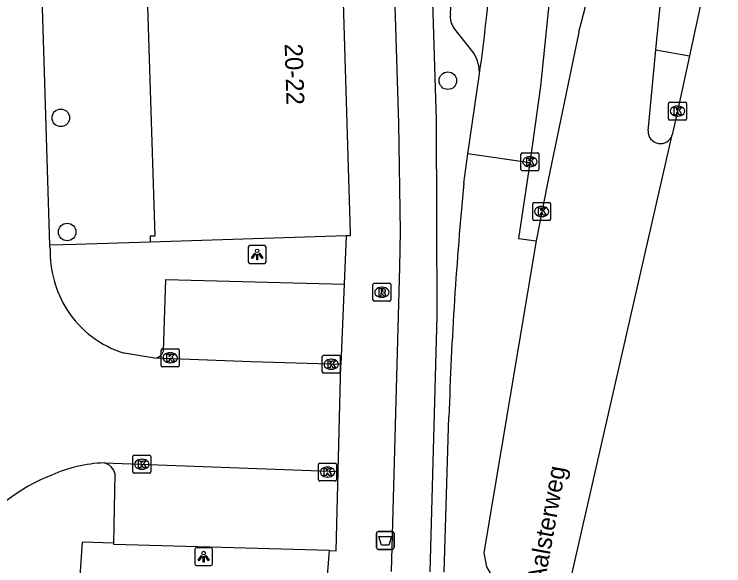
# Model space of a CAD drawing. Extents: x 161402 to 161933, y 381650 to 382313.
# Drawn here: x 161889.94 to 161929.57, y 382075.91 to 382106.69 of the extents above; entities that cross this region are included whole.
import ezdxf

# ---------------------------------------------------------------- set-up
doc = ezdxf.new("R2010")
doc.units = 0
for name, color, linetype in [('IMGEO_Afvalbak', 7, 'Continuous'), ('IMGEO_Boom', 7, 'Continuous'), ('IMGEO_Fietspad_open', 7, 'Continuous'), ('IMGEO_Kolk', 7, 'Continuous'), ('IMGEO_Lichtpunt', 7, 'Continuous'), ('IMGEO_Muur', 7, 'Continuous'), ('IMGEO_Openbare_ruimte_label', 7, 'Continuous'), ('IMGEO_OVBaan_gesloten', 7, 'Continuous'), ('IMGEO_Pand', 7, 'Continuous'), ('IMGEO_Pand_nummerreeks', 7, 'Continuous'), ('IMGEO_Parkeervlak_open', 7, 'Continuous'), ('IMGEO_Rijbaan_lokaal_gesloten', 7, 'Continuous'), ('IMGEO_Rijbaan_lokaal_open', 7, 'Continuous'), ('IMGEO_Rioolput', 7, 'Continuous'), ('IMGEO_Verkeerseiland_open', 7, 'Continuous'), ('IMGEO_Voetpad_open', 7, 'Continuous')]:
    doc.layers.add(name, color=color, linetype=linetype)

msp = doc.modelspace()

# ---------------------------------------------------------------- linework, layer by layer
at = {"layer": 'IMGEO_Afvalbak'}
for p, q in [((161910.171, 382076.92), (161910.171, 382077.72)), ((161910.171, 382077.72), (161910.171, 382076.92)), ((161910.271, 382077.82), (161911.061, 382077.82)), ((161911.061, 382077.82), (161910.271, 382077.82)), ((161911.161, 382077.72), (161911.161, 382076.92)), ((161911.161, 382076.92), (161911.161, 382077.72)), ((161911.061, 382076.82), (161910.271, 382076.82)), ((161910.271, 382076.82), (161911.061, 382076.82))]:
    msp.add_line(p, q, dxfattribs=at)
msp.add_lwpolyline([(161910.314, 382077.534), (161911.018, 382077.534), (161910.869, 382077.064), (161910.463, 382077.064), (161910.314, 382077.534)], dxfattribs=at)
for centre, start, end in [((161910.271, 382077.72), 90, 180), ((161910.271, 382077.72), 90, 180), ((161911.061, 382077.72), 0, 90), ((161911.061, 382077.72), 360, 90), ((161910.271, 382076.92), 180, 270), ((161910.271, 382076.92), 180, 270), ((161911.061, 382076.92), 270, 0), ((161911.061, 382076.92), 270, 0)]:
    msp.add_arc(centre, 0.1, start, end, dxfattribs=at)
at = {"layer": 'IMGEO_Boom'}
for centre in [(161914.164, 382102.973), (161892.545, 382100.904), (161892.901, 382094.534)]:
    msp.add_circle(centre, 0.489, dxfattribs=at)
at = {"layer": 'IMGEO_Fietspad_open'}
for points in [[(161911.019, 382075.595), (161911.485, 382092.573), (161911.516, 382094.566), (161911.423, 382100.579), (161910.052, 382144.744)], [(161912.16, 382144.813), (161912.252, 382141.473), (161913.518, 382100.778), (161913.546, 382089.832), (161913.149, 382075.567)]]:
    msp.add_lwpolyline(points, dxfattribs=at)
at = {"layer": 'IMGEO_Kolk'}
for p, q in [((161926.487, 382100.851), (161926.487, 382101.703)), ((161926.562, 382101.777), (161927.414, 382101.777)), ((161926.975, 382101.557), (161927, 382101.557)), ((161927.488, 382101.703), (161927.488, 382100.851)), ((161927.414, 382100.777), (161926.562, 382100.777)), ((161926.998, 382100.997), (161926.973, 382100.997)), ((161918.246, 382098.026), (161918.246, 382098.878)), ((161918.321, 382098.952), (161919.173, 382098.952)), ((161918.734, 382098.732), (161918.759, 382098.732)), ((161919.247, 382098.878), (161919.247, 382098.026)), ((161919.173, 382097.952), (161918.321, 382097.952)), ((161918.757, 382098.172), (161918.732, 382098.172)), ((161918.901, 382095.25), (161918.901, 382096.102)), ((161918.976, 382096.176), (161919.828, 382096.176)), ((161919.389, 382095.956), (161919.414, 382095.956)), ((161919.902, 382096.102), (161919.902, 382095.25)), ((161919.828, 382095.176), (161918.976, 382095.176)), ((161919.412, 382095.396), (161919.387, 382095.396)), ((161898.23, 382088.013), (161899.082, 382088.013)), ((161898.155, 382087.087), (161898.155, 382087.939)), ((161898.643, 382087.793), (161898.668, 382087.793)), ((161899.156, 382087.939), (161899.156, 382087.087)), ((161907.149, 382086.726), (161907.149, 382087.578)), ((161907.224, 382087.652), (161908.076, 382087.652)), ((161908.15, 382087.578), (161908.15, 382086.726)), ((161898.666, 382087.233), (161898.641, 382087.233)), ((161907.637, 382087.432), (161907.662, 382087.432)), ((161899.082, 382087.013), (161898.23, 382087.013)), ((161907.66, 382086.872), (161907.635, 382086.872)), ((161908.076, 382086.652), (161907.224, 382086.652)), ((161896.643, 382082.074), (161897.495, 382082.074)), ((161896.568, 382081.148), (161896.568, 382082)), ((161897.056, 382081.854), (161897.081, 382081.854)), ((161897.569, 382082), (161897.569, 382081.148)), ((161907.014, 382081.64), (161907.866, 382081.64)), ((161897.079, 382081.294), (161897.054, 382081.294)), ((161906.939, 382080.714), (161906.939, 382081.566)), ((161907.427, 382081.42), (161907.452, 382081.42)), ((161907.94, 382081.566), (161907.94, 382080.714)), ((161897.495, 382081.074), (161896.643, 382081.074)), ((161907.45, 382080.86), (161907.425, 382080.86)), ((161907.866, 382080.64), (161907.014, 382080.64))]:
    msp.add_line(p, q, dxfattribs=at)
for points in [[(161926.487, 382100.851), (161926.487, 382101.703)], [(161926.562, 382101.777), (161927.414, 382101.777)], [(161926.808, 382101.477), (161926.931, 382101.477), (161926.931, 382101.326), (161927.061, 382101.477), (161927.225, 382101.477), (161927.079, 382101.326), (161927.232, 382101.077), (161927.08, 382101.077), (161926.995, 382101.241), (161926.931, 382101.174), (161926.931, 382101.077), (161926.808, 382101.077), (161926.808, 382101.477)], [(161927.488, 382101.703), (161927.488, 382100.851)], [(161927.414, 382100.777), (161926.562, 382100.777)], [(161918.246, 382098.026), (161918.246, 382098.878)], [(161918.321, 382098.952), (161919.173, 382098.952)], [(161918.567, 382098.652), (161918.69, 382098.652), (161918.69, 382098.501), (161918.82, 382098.652), (161918.984, 382098.652), (161918.838, 382098.501), (161918.991, 382098.252), (161918.839, 382098.252), (161918.754, 382098.416), (161918.69, 382098.349), (161918.69, 382098.252), (161918.567, 382098.252), (161918.567, 382098.652)], [(161919.247, 382098.878), (161919.247, 382098.026)], [(161919.173, 382097.952), (161918.321, 382097.952)], [(161918.901, 382095.25), (161918.901, 382096.102)], [(161918.976, 382096.176), (161919.828, 382096.176)], [(161919.902, 382096.102), (161919.902, 382095.25)], [(161919.222, 382095.876), (161919.345, 382095.876), (161919.345, 382095.725), (161919.475, 382095.876), (161919.639, 382095.876), (161919.493, 382095.725), (161919.646, 382095.476), (161919.494, 382095.476), (161919.409, 382095.64), (161919.345, 382095.573), (161919.345, 382095.476), (161919.222, 382095.476), (161919.222, 382095.876)], [(161919.828, 382095.176), (161918.976, 382095.176)], [(161898.23, 382088.013), (161899.082, 382088.013)], [(161898.155, 382087.087), (161898.155, 382087.939)], [(161898.476, 382087.713), (161898.599, 382087.713), (161898.599, 382087.562), (161898.729, 382087.713), (161898.893, 382087.713), (161898.747, 382087.562), (161898.9, 382087.313), (161898.748, 382087.313), (161898.663, 382087.477), (161898.599, 382087.41), (161898.599, 382087.313), (161898.476, 382087.313), (161898.476, 382087.713)], [(161899.156, 382087.939), (161899.156, 382087.087)], [(161907.149, 382086.726), (161907.149, 382087.578)], [(161907.224, 382087.652), (161908.076, 382087.652)], [(161908.15, 382087.578), (161908.15, 382086.726)], [(161907.47, 382087.352), (161907.593, 382087.352), (161907.593, 382087.201), (161907.723, 382087.352), (161907.887, 382087.352), (161907.741, 382087.201), (161907.894, 382086.952), (161907.742, 382086.952), (161907.657, 382087.116), (161907.593, 382087.049), (161907.593, 382086.952), (161907.47, 382086.952), (161907.47, 382087.352)], [(161899.082, 382087.013), (161898.23, 382087.013)], [(161908.076, 382086.652), (161907.224, 382086.652)], [(161896.643, 382082.074), (161897.495, 382082.074)], [(161896.568, 382081.148), (161896.568, 382082)], [(161896.889, 382081.774), (161897.012, 382081.774), (161897.012, 382081.623), (161897.142, 382081.774), (161897.306, 382081.774), (161897.16, 382081.623), (161897.313, 382081.374), (161897.161, 382081.374), (161897.076, 382081.538), (161897.012, 382081.471), (161897.012, 382081.374), (161896.889, 382081.374), (161896.889, 382081.774)], [(161897.569, 382082), (161897.569, 382081.148)], [(161907.014, 382081.64), (161907.866, 382081.64)], [(161906.939, 382080.714), (161906.939, 382081.566)], [(161907.26, 382081.34), (161907.383, 382081.34), (161907.383, 382081.189), (161907.513, 382081.34), (161907.677, 382081.34), (161907.531, 382081.189), (161907.684, 382080.94), (161907.532, 382080.94), (161907.447, 382081.104), (161907.383, 382081.037), (161907.383, 382080.94), (161907.26, 382080.94), (161907.26, 382081.34)], [(161907.94, 382081.566), (161907.94, 382080.714)], [(161897.495, 382081.074), (161896.643, 382081.074)], [(161907.866, 382080.64), (161907.014, 382080.64)]]:
    msp.add_lwpolyline(points, dxfattribs=at)
for centre, start, end in [((161926.564, 382101.701), 91.552, 178.448), ((161926.564, 382101.701), 91.552, 178.448), ((161927.412, 382101.701), 1.552, 88.448), ((161927.412, 382101.701), 1.552, 88.448), ((161926.564, 382100.853), 181.552, 268.448), ((161926.564, 382100.853), 181.552, 268.448), ((161927.412, 382100.853), 271.552, 358.448), ((161927.412, 382100.853), 271.552, 358.448), ((161918.323, 382098.876), 91.552, 178.448), ((161918.323, 382098.876), 91.552, 178.448), ((161919.171, 382098.876), 1.552, 88.448), ((161919.171, 382098.876), 1.552, 88.448), ((161918.323, 382098.028), 181.552, 268.448), ((161918.323, 382098.028), 181.552, 268.448), ((161919.171, 382098.028), 271.552, 358.448), ((161919.171, 382098.028), 271.552, 358.448), ((161918.978, 382096.1), 91.552, 178.448), ((161918.978, 382096.1), 91.552, 178.448), ((161919.826, 382096.1), 1.552, 88.448), ((161919.826, 382096.1), 1.552, 88.448), ((161918.978, 382095.252), 181.552, 268.448), ((161918.978, 382095.252), 181.552, 268.448), ((161919.826, 382095.252), 271.552, 358.448), ((161919.826, 382095.252), 271.552, 358.448), ((161898.232, 382087.937), 91.552, 178.448), ((161898.232, 382087.937), 91.552, 178.448), ((161899.08, 382087.937), 1.552, 88.448), ((161899.08, 382087.937), 1.552, 88.448), ((161907.226, 382087.576), 91.552, 178.448), ((161907.226, 382087.576), 91.552, 178.448), ((161908.074, 382087.576), 1.552, 88.448), ((161908.074, 382087.576), 1.552, 88.448), ((161898.232, 382087.089), 181.552, 268.448), ((161898.232, 382087.089), 181.552, 268.448), ((161899.08, 382087.089), 271.552, 358.448), ((161899.08, 382087.089), 271.552, 358.448), ((161907.226, 382086.728), 181.552, 268.448), ((161907.226, 382086.728), 181.552, 268.448), ((161908.074, 382086.728), 271.552, 358.448), ((161908.074, 382086.728), 271.552, 358.448), ((161896.645, 382081.998), 91.552, 178.448), ((161896.645, 382081.998), 91.552, 178.448), ((161897.493, 382081.998), 1.552, 88.448), ((161897.493, 382081.998), 1.552, 88.448), ((161907.016, 382081.564), 91.552, 178.448), ((161907.016, 382081.564), 91.552, 178.448), ((161907.864, 382081.564), 1.552, 88.448), ((161907.864, 382081.564), 1.552, 88.448), ((161896.645, 382081.15), 181.552, 268.448), ((161896.645, 382081.15), 181.552, 268.448), ((161897.493, 382081.15), 271.552, 358.448), ((161897.493, 382081.15), 271.552, 358.448), ((161907.016, 382080.716), 181.552, 268.448), ((161907.016, 382080.716), 181.552, 268.448), ((161907.864, 382080.716), 271.552, 358.448), ((161907.864, 382080.716), 271.552, 358.448)]:
    msp.add_arc(centre, 0.0765, start, end, dxfattribs=at)
for centre, major_axis, ratio, start_param, end_param in [((161926.974, 382101.277), (-0.387, 0.002), 0.722429, 4.712389, 7.853982), ((161926.999, 382101.277), (-0.39, 0.002), 0.717154, 1.570796, 4.712389), ((161918.733, 382098.452), (-0.387, 0.002), 0.722429, 4.712389, 7.853982), ((161918.758, 382098.452), (-0.39, 0.002), 0.717154, 1.570796, 4.712389), ((161919.388, 382095.676), (-0.387, 0.002), 0.722429, 4.712389, 7.853982), ((161919.413, 382095.676), (-0.39, 0.002), 0.717154, 1.570796, 4.712389), ((161898.642, 382087.513), (-0.387, 0.002), 0.722429, 4.712389, 7.853982), ((161898.667, 382087.513), (-0.39, 0.002), 0.717154, 1.570796, 4.712389), ((161907.636, 382087.152), (-0.387, 0.002), 0.722429, 4.712389, 7.853982), ((161907.661, 382087.152), (-0.39, 0.002), 0.717154, 1.570796, 4.712389), ((161897.055, 382081.574), (-0.387, 0.002), 0.722429, 4.712389, 7.853982), ((161897.08, 382081.574), (-0.39, 0.002), 0.717154, 1.570796, 4.712389), ((161907.426, 382081.14), (-0.387, 0.002), 0.722429, 4.712389, 7.853982), ((161907.451, 382081.14), (-0.39, 0.002), 0.717154, 1.570796, 4.712389)]:
    msp.add_ellipse(centre, major_axis=major_axis, ratio=ratio, start_param=start_param, end_param=end_param, dxfattribs=at)
at = {"layer": 'IMGEO_Lichtpunt'}
for p, q in [((161903.011, 382093.682), (161903.011, 382092.875)), ((161903.011, 382093.682), (161903.011, 382092.875)), ((161903.913, 382093.777), (161903.105, 382093.777)), ((161903.913, 382093.777), (161903.105, 382093.777)), ((161904.007, 382092.875), (161904.007, 382093.682)), ((161904.007, 382092.875), (161904.007, 382093.682)), ((161903.105, 382092.781), (161903.913, 382092.781)), ((161903.105, 382092.781), (161903.913, 382092.781)), ((161900.931, 382076.914), (161900.123, 382076.914)), ((161900.931, 382076.914), (161900.123, 382076.914)), ((161900.029, 382076.819), (161900.029, 382076.012)), ((161900.029, 382076.819), (161900.029, 382076.012)), ((161901.025, 382076.012), (161901.025, 382076.819)), ((161901.025, 382076.012), (161901.025, 382076.819)), ((161900.123, 382075.918), (161900.931, 382075.918)), ((161900.123, 382075.918), (161900.931, 382075.918))]:
    msp.add_line(p, q, dxfattribs=at)
for points in [[(161903.385, 382093.346), (161903.424, 382093.318), (161903.236, 382093.056), (161903.198, 382093.083), (161903.385, 382093.346)], [(161903.487, 382093.298), (161903.534, 382093.298), (161903.534, 382092.976), (161903.487, 382092.976), (161903.487, 382093.298)], [(161903.597, 382093.318), (161903.635, 382093.345), (161903.822, 382093.083), (161903.783, 382093.055), (161903.597, 382093.318)], [(161900.403, 382076.483), (161900.442, 382076.455), (161900.254, 382076.193), (161900.216, 382076.22), (161900.403, 382076.483)], [(161900.615, 382076.455), (161900.653, 382076.482), (161900.84, 382076.22), (161900.801, 382076.192), (161900.615, 382076.455)], [(161900.505, 382076.435), (161900.552, 382076.435), (161900.552, 382076.113), (161900.505, 382076.113), (161900.505, 382076.435)]]:
    msp.add_lwpolyline(points, dxfattribs=at)
for centre in [(161903.51, 382093.48), (161900.528, 382076.617)]:
    msp.add_circle(centre, 0.0994, dxfattribs=at)
for centre, start, end in [((161903.105, 382093.682), 90, 180), ((161903.105, 382093.682), 90, 180), ((161903.913, 382093.682), 0, 90), ((161903.913, 382093.682), 0, 90), ((161903.105, 382092.875), 180, 270), ((161903.105, 382092.875), 180, 270), ((161903.913, 382092.875), 270, 0), ((161903.913, 382092.875), 270, 360), ((161900.123, 382076.819), 90, 180), ((161900.123, 382076.819), 90, 180), ((161900.931, 382076.819), 0, 90), ((161900.931, 382076.819), 0, 90), ((161900.123, 382076.012), 180, 270), ((161900.123, 382076.012), 180, 270), ((161900.931, 382076.012), 270, 0), ((161900.931, 382076.012), 270, 360)]:
    msp.add_arc(centre, 0.0946, start, end, dxfattribs=at)
at = {"layer": 'IMGEO_Muur'}
msp.add_lwpolyline([(161897.538, 382093.965), (161893.381, 382093.835)], dxfattribs=at)
at = {"layer": 'IMGEO_OVBaan_gesloten'}
for points in [[(161929.574, 382113.249), (161927.659, 382104.365)], [(161927.659, 382104.365), (161926.989, 382101.276), (161926.695, 382099.95)], [(161894.174, 381930.698), (161920.066, 382070.485), (161920.568, 382072.989), (161920.797, 382074.121), (161926.695, 382099.95)]]:
    msp.add_lwpolyline(points, dxfattribs=at)
at = {"layer": 'IMGEO_Pand'}
for points in [[(161908.217, 382110.391), (161908.71, 382094.477), (161908.715, 382094.318), (161908.487, 382094.311)], [(161897.292, 382110.047), (161897.788, 382094.302), (161897.528, 382094.294), (161897.538, 382093.965)], [(161908.487, 382094.311), (161897.538, 382093.965)]]:
    msp.add_lwpolyline(points, dxfattribs=at)
at = {"layer": 'IMGEO_Parkeervlak_open'}
for points in [[(161914.31, 382106.685), (161914.634, 382112.711), (161914.66, 382115.753), (161914.358, 382131.92)], [(161915.49, 382104.68), (161914.504, 382105.919)]]:
    msp.add_lwpolyline(points, dxfattribs=at)
for centre, radius, start, end in [((161915.249, 382106.515), 0.954, 169.7585, 218.6657), ((161913.912, 382103.433), 2.011, 353.9448, 38.3191)]:
    msp.add_arc(centre, radius, start, end, dxfattribs=at)
at = {"layer": 'IMGEO_Rijbaan_lokaal_gesloten'}
for points in [[(161925.781, 382104.703), (161927.423, 382121.095), (161927.747, 382126.278), (161927.762, 382128.469)], [(161921.473, 382105.692), (161919.741, 382097.352), (161919.101, 382094.04)], [(161925.341, 382100.172), (161925.781, 382104.703)], [(161919.101, 382094.04), (161916.164, 382076.625), (161916.325, 382075.85), (161916.704, 382075.178)]]:
    msp.add_lwpolyline(points, dxfattribs=at)
for centre, radius, start, end in [((161814.253, 382134.176), 110.939, 345.12266, 353.63931), ((161926.034, 382100.159), 0.693, 178.9321, 342.4453)]:
    msp.add_arc(centre, radius, start, end, dxfattribs=at)
at = {"layer": 'IMGEO_Rijbaan_lokaal_open'}
for points in [[(161891.937, 382093.79), (161890.273, 382147.456)], [(161919.967, 382109.09), (161919.943, 382108.679), (161919.334, 382102.678), (161918.737, 382098.388)], [(161915.287, 382098.891), (161915.912, 382103.221)], [(161915.059, 382097.255), (161915.287, 382098.891)], [(161918.737, 382098.388), (161915.287, 382098.891)], [(161918.737, 382098.388), (161918.107, 382094.176), (161919.101, 382094.04)], [(161891.943, 382093.602), (161891.937, 382093.79)], [(161897.789, 382087.498), (161897.658, 382087.503), (161896.1, 382087.766)], [(161908.19, 382087.143), (161903.185, 382087.293), (161897.789, 382087.498)], [(161908.04, 382081.166), (161908.19, 382087.143)], [(161913.954, 382075.562), (161914.223, 382084.227)], [(161894.96, 382081.654), (161908.04, 382081.166)]]:
    msp.add_lwpolyline(points, dxfattribs=at)
for centre, radius, start, end in [((161829.113, 382115.663), 87.686, 351.84266, 1.22982), ((162111.024, 382078.139), 196.895, 174.4286, 178.22819), ((161898.156, 382093.493), 6.214, 178.9986, 211.9958), ((161897.813, 382093.366), 5.856, 212.7135, 252.9897), ((161895.298, 382073.653), 8.008, 92.4194, 114.0135), ((161895.614, 382071.735), 9.901, 111.1686, 144.6677)]:
    msp.add_arc(centre, radius, start, end, dxfattribs=at)
at = {"layer": 'IMGEO_Rioolput'}
for p, q in [((161909.979, 382090.743), (161909.979, 382091.595)), ((161910.054, 382091.669), (161910.906, 382091.669)), ((161910.98, 382091.595), (161910.98, 382090.743)), ((161910.467, 382091.449), (161910.492, 382091.449)), ((161910.49, 382090.889), (161910.465, 382090.889)), ((161910.906, 382090.669), (161910.054, 382090.669))]:
    msp.add_line(p, q, dxfattribs=at)
for points in [[(161909.979, 382090.743), (161909.979, 382091.595)], [(161910.054, 382091.669), (161910.906, 382091.669)], [(161910.98, 382091.595), (161910.98, 382090.743)], [(161910.568, 382091.367), (161910.316, 382091.369), (161910.316, 382090.969)], [(161910.316, 382090.969), (161910.44, 382090.969), (161910.44, 382091.131), (161910.451, 382091.131)], [(161910.494, 382091.288), (161910.44, 382091.288), (161910.44, 382091.207)], [(161910.44, 382091.207), (161910.492, 382091.207)], [(161910.498, 382091.102), (161910.569, 382090.969), (161910.709, 382090.969), (161910.644, 382091.095)], [(161910.906, 382090.669), (161910.054, 382090.669)]]:
    msp.add_lwpolyline(points, dxfattribs=at)
for centre, radius, start, end in [((161910.056, 382091.593), 0.0765, 91.552, 178.448), ((161910.056, 382091.593), 0.0765, 91.552, 178.448), ((161910.904, 382091.593), 0.0765, 1.552, 88.448), ((161910.904, 382091.593), 0.0765, 1.552, 88.448), ((161910.45, 382091.078), 0.0533, 26.0293, 88.6989), ((161910.476, 382091.396), 0.19, 274.7715, 282.9687), ((161910.5, 382091.192), 0.0964, 77.0061, 93.1865), ((161910.514, 382091.249), 0.0378, 276.6634, 79.6772), ((161910.567, 382091.257), 0.109, 350.3612, 89.416), ((161910.565, 382091.257), 0.112, 277.5842, 350.9817), ((161910.549, 382091.042), 0.108, 29.5134, 73.7905), ((161910.056, 382090.745), 0.0765, 181.552, 268.448), ((161910.056, 382090.745), 0.0765, 181.552, 268.448), ((161910.904, 382090.745), 0.0765, 271.552, 358.448), ((161910.904, 382090.745), 0.0765, 271.552, 358.448)]:
    msp.add_arc(centre, radius, start, end, dxfattribs=at)
for centre, major_axis, ratio, start_param, end_param in [((161910.466, 382091.169), (-0.387, 0.002), 0.722429, 4.712389, 7.853982), ((161910.491, 382091.169), (-0.39, 0.002), 0.717154, 1.570796, 4.712389)]:
    msp.add_ellipse(centre, major_axis=major_axis, ratio=ratio, start_param=start_param, end_param=end_param, dxfattribs=at)
at = {"layer": 'IMGEO_Verkeerseiland_open'}
msp.add_lwpolyline([(161925.781, 382104.703), (161927.659, 382104.365)], dxfattribs=at)
at = {"layer": 'IMGEO_Voetpad_open'}
for points in [[(161908.487, 382094.311), (161908.372, 382091.621)], [(161897.538, 382093.965), (161893.381, 382093.835), (161891.937, 382093.79)], [(161898.277, 382087.89), (161898.418, 382091.877), (161908.372, 382091.621)], [(161908.372, 382091.621), (161908.19, 382087.143)], [(161895.501, 382077.17), (161895.59, 382081.019)], [(161907.56, 382076.762), (161907.929, 382076.752), (161908.04, 382081.166)], [(161895.501, 382077.17), (161893.731, 382077.231), (161893.044, 382067.129)], [(161907.56, 382076.762), (161895.499, 382077.1), (161895.501, 382077.17)], [(161907.356, 382074.185), (161907.56, 382076.762)]]:
    msp.add_lwpolyline(points, dxfattribs=at)
for centre, radius, start, end in [((161897.744, 382088.054), 0.558, 274.6532, 342.8951), ((161894.733, 382080.798), 0.885, 14.4321, 75.115)]:
    msp.add_arc(centre, radius, start, end, dxfattribs=at)

# ---------------------------------------------------------------- texts
at = {"layer": 'IMGEO_Openbare_ruimte_label'}
msp.add_text('Aalsterweg', height=1, rotation=79.5773, dxfattribs=at).set_placement((161919.558, 382074.882))
at = {"layer": 'IMGEO_Pand_nummerreeks'}
msp.add_text('20-22', height=1, rotation=271.7989, dxfattribs=at).set_placement((161905.047, 382105.027))

doc.saveas('drawing.dxf')
